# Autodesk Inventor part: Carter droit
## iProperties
Shininess: 64.0
Length Units: 11269
Angle Units: 11279
Time Units: 11290
Mass Units: 11283
Length Display Precision: 3
Angle Display Precision: 2
Compacted: True
Part Number: Carter droit
Document SubType Name: Modeling
Created: 2003-05
Material: Delrin - Noir
Designer: Philippe
Density: 0.0
Volumn: 0.0
Area: 0.0
PropertySet Name: Model Information
Control State: 0
Master: False
Checked Out: False
Author: Philippe
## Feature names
1. Collerette de centrage [Extrusion]
2. 6 Pans creux de 7 [Extrusion]
3. Extrusion3
4. Corps dérivé1 [Tagging]
